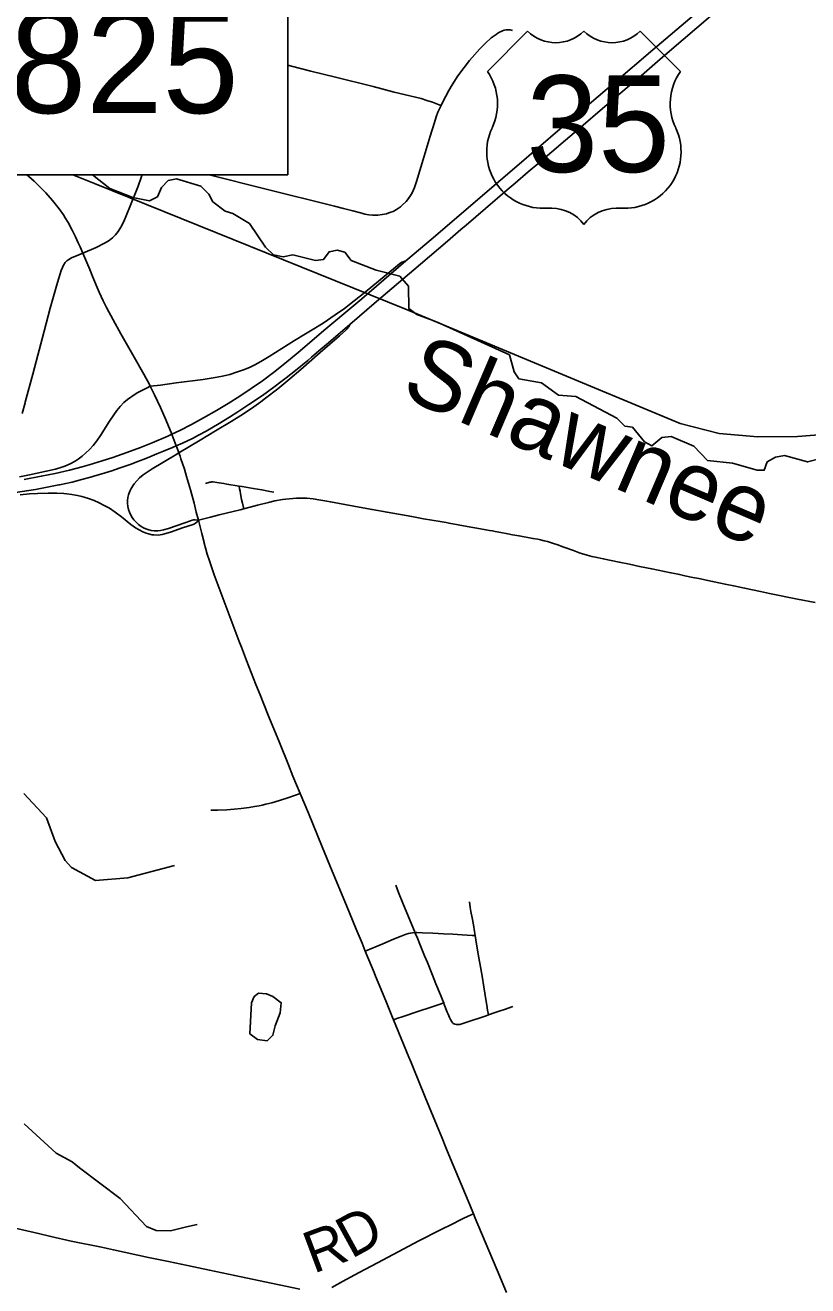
# Model space of a CAD drawing. Extents: x -1.4 to 35.4, y 0 to 22.
# Drawn here: x 13.773 to 14.841, y 16.794 to 18.515 of the extents above; entities that cross this region are included whole.
import ezdxf

# ---------------------------------------------------------------- set-up
doc = ezdxf.new("R2010")
doc.units = 0
for name, color, linetype in [('GM_X_City_Street', 7, 'Continuous'), ('GM_X_County_Road', 7, 'Continuous'), ('GM_X_Interchange_Ramps', 7, 'Continuous'), ('GM_X_Minor_Lake', 7, 'Continuous'), ('GM_X_Minor_River', 7, 'Continuous'), ('GM_X_Minor_River_Text', 7, 'Continuous'), ('GM_X_Rail_Line', 7, 'Continuous'), ('GM_X_Township_Road', 7, 'Continuous'), ('GM_X_Township_Road_Text', 7, 'Continuous'), ('GM_X_US_Location', 7, 'Continuous'), ('GM_X_US_Route', 7, 'Continuous'), ('GM_X_US_Shield', 7, 'Continuous'), ('SH_Data', 7, 'Continuous')]:
    doc.layers.add(name, color=color, linetype=linetype)

msp = doc.modelspace()

# ---------------------------------------------------------------- linework, layer by layer
at = {"layer": 'GM_X_City_Street'}
for points in [[(14.0238, 18.3109), (14.1, 18.2917), (14.1952, 18.2679), (14.2072, 18.2648), (14.22, 18.2615), (14.2306, 18.2587), (14.2338, 18.2578), (14.2365, 18.2572), (14.2392, 18.2566), (14.2421, 18.2562), (14.2469, 18.2557), (14.2505, 18.2555), (14.2542, 18.2558), (14.2603, 18.2564), (14.2633, 18.257), (14.2663, 18.2577), (14.2693, 18.2587), (14.2721, 18.2596), (14.2751, 18.2609), (14.2776, 18.2622), (14.2796, 18.2633), (14.2823, 18.2651), (14.285, 18.2671), (14.2875, 18.2693), (14.2928, 18.2744), (14.2963, 18.2786), (14.2997, 18.2837), (14.3014, 18.287), (14.3031, 18.2902), (14.3044, 18.2933), (14.3053, 18.2961), (14.3071, 18.3017), (14.3162, 18.3315), (14.3255, 18.3637), (14.3314, 18.3821), (14.3341, 18.3899), (14.3364, 18.3963), (14.3393, 18.4027), (14.3405, 18.4053), (14.3421, 18.4087), (14.3469, 18.4181), (14.3512, 18.4259), (14.3559, 18.4338), (14.3637, 18.4458), (14.372, 18.4575), (14.3794, 18.4667), (14.3933, 18.4827), (14.4013, 18.4906), (14.4092, 18.4977), (14.4157, 18.5026), (14.4182, 18.5043), (14.4205, 18.5056), (14.4225, 18.5066), (14.4246, 18.5075), (14.4269, 18.5082), (14.4299, 18.5088), (14.4324, 18.5089), (14.4348, 18.5087), (14.438, 18.508)], [(14.1312, 18.4607), (14.1363, 18.459), (14.1629, 18.4524), (14.1966, 18.444), (14.2479, 18.4312), (14.2767, 18.4238), (14.3136, 18.4148), (14.3213, 18.4125), (14.3291, 18.4099), (14.3381, 18.4063), (14.3405, 18.4053)], [(13.8515, 18.204), (13.8699, 18.2114), (13.8822, 18.218), (13.8876, 18.2213), (13.892, 18.2249), (13.896, 18.2289), (13.8996, 18.2333), (13.9033, 18.2392), (13.9073, 18.247), (13.9155, 18.2672), (13.9269, 18.2954), (13.9312, 18.3071), (13.9324, 18.3109)]]:
    msp.add_lwpolyline(points, dxfattribs=at)
at = {"layer": 'GM_X_County_Road'}
msp.add_line((13.7729, 18.0004), (13.783, 18.0386), dxfattribs=at)
for points in [[(13.783, 18.0386), (13.7987, 18.0973), (13.807, 18.1287), (13.8171, 18.1637), (13.8219, 18.1803), (13.8235, 18.1842), (13.8252, 18.1876), (13.8275, 18.191), (13.8297, 18.1932), (13.8323, 18.1952), (13.8359, 18.1973), (13.8461, 18.2017), (13.8515, 18.204)], [(13.7687, 17.9849), (13.7726, 17.9994), (13.7729, 18.0004)]]:
    msp.add_lwpolyline(points, dxfattribs=at)
at = {"layer": 'GM_X_Interchange_Ramps'}
for points in [[(14.2924, 18.1931), (14.2887, 18.1919), (14.2872, 18.1914), (14.2857, 18.1906), (14.2838, 18.1892), (14.2757, 18.1825), (14.2657, 18.1742), (14.237, 18.1506), (14.222, 18.1385), (14.2087, 18.1284), (14.196, 18.1194), (14.1794, 18.1084), (14.1647, 18.0991), (14.1557, 18.0936), (14.1403, 18.0843), (14.1061, 18.0628), (14.0944, 18.0558), (14.0862, 18.0513), (14.0789, 18.0478), (14.0709, 18.0445), (14.0615, 18.0412), (14.052, 18.0383), (14.0423, 18.0359), (14.032, 18.0339), (14.016, 18.0314), (13.979, 18.0266), (13.9575, 18.0237), (13.9435, 18.022)], [(13.9776, 17.928), (13.9826, 17.931), (14.0118, 17.9486), (14.0326, 17.9611), (14.0539, 17.974), (14.0708, 17.9846), (14.0848, 17.9939), (14.0944, 18.0007), (14.1009, 18.0056), (14.1178, 18.0187), (14.134, 18.032), (14.1491, 18.0449), (14.1756, 18.0681), (14.2019, 18.0911), (14.2105, 18.0987), (14.2123, 18.1004), (14.2134, 18.1018), (14.2145, 18.1034), (14.216, 18.1063)], [(13.9435, 18.022), (13.9391, 18.0198), (13.9294, 18.0151), (13.9264, 18.0134), (13.9228, 18.0112), (13.9125, 18.0039), (13.9076, 17.9997), (13.9025, 17.9942), (13.898, 17.989), (13.8936, 17.9831), (13.8878, 17.9743), (13.8756, 17.9548), (13.8707, 17.9476), (13.8657, 17.9413), (13.8607, 17.9357), (13.8558, 17.931), (13.8506, 17.9265), (13.8451, 17.9224), (13.841, 17.9198), (13.8344, 17.9162), (13.827, 17.913), (13.8229, 17.9116), (13.814, 17.909), (13.7994, 17.9057), (13.7785, 17.9009), (13.7648, 17.8985)], [(14.0092, 17.8391), (14.0047, 17.8394), (14.0027, 17.8394), (14.0008, 17.8391), (13.9983, 17.8384), (13.9907, 17.8356), (13.9684, 17.8278), (13.9618, 17.8259), (13.9576, 17.8251), (13.9539, 17.8247), (13.9489, 17.8247), (13.9446, 17.8252), (13.9416, 17.8259), (13.9375, 17.8272), (13.9341, 17.8288), (13.9309, 17.8307), (13.9274, 17.8333), (13.9242, 17.8362), (13.9213, 17.8395), (13.9187, 17.843), (13.9168, 17.8462), (13.915, 17.8501), (13.9138, 17.8537), (13.9129, 17.8579), (13.9125, 17.8622), (13.9126, 17.866), (13.9131, 17.8703), (13.9139, 17.8739), (13.9155, 17.8786), (13.9168, 17.8814), (13.9196, 17.8862), (13.9214, 17.8888), (13.925, 17.893), (13.929, 17.8969), (13.9338, 17.9009), (13.9394, 17.9049), (13.9462, 17.9092), (13.9776, 17.928)], [(13.7661, 17.8739), (13.7785, 17.8751), (13.7897, 17.8757), (13.804, 17.876), (13.8162, 17.8759), (13.8256, 17.8755), (13.8298, 17.8751), (13.8364, 17.8742), (13.8413, 17.8734), (13.8441, 17.8728), (13.8499, 17.8715), (13.8533, 17.8705), (13.8592, 17.8687), (13.8668, 17.8661), (13.8738, 17.863), (13.8807, 17.8594), (13.8877, 17.8554), (13.8956, 17.85), (13.9041, 17.8435), (13.9168, 17.8334), (13.9234, 17.8288), (13.9282, 17.8259), (13.9332, 17.8234), (13.9378, 17.8215)], [(13.9378, 17.8215), (13.9413, 17.8204), (13.9462, 17.8193), (13.9486, 17.819), (13.9542, 17.8189), (13.9597, 17.8197), (13.9628, 17.8204), (13.9711, 17.8229), (13.9875, 17.8286), (14.0021, 17.8333), (14.0041, 17.8341), (14.0055, 17.8349), (14.007, 17.8363), (14.0092, 17.8391)]]:
    msp.add_lwpolyline(points, dxfattribs=at)
at = {"layer": 'GM_X_Minor_Lake'}
for points in [[(14.0796, 17.1378), (14.0901, 17.1297), (14.103, 17.1279), (14.1111, 17.1358), (14.1143, 17.1486), (14.1211, 17.1663), (14.1225, 17.18), (14.1108, 17.1885), (14.1022, 17.1925), (14.0912, 17.1934), (14.0854, 17.1886), (14.0818, 17.1799)], [(14.0818, 17.1799), (14.0796, 17.1378)]]:
    msp.add_lwpolyline(points, dxfattribs=at)
at = {"layer": 'GM_X_Minor_River'}
for points in [[(13.8645, 18.3109), (13.8882, 18.2923), (13.9199, 18.28), (13.9426, 18.2754), (13.9533, 18.2809), (13.9589, 18.2934), (13.9682, 18.3031), (13.9792, 18.3052), (14.0128, 18.2955), (14.0236, 18.2843), (14.0288, 18.2739), (14.0457, 18.2611), (14.0562, 18.2579), (14.0792, 18.2442), (14.101, 18.2119), (14.1118, 18.2015), (14.1251, 18.1989), (14.138, 18.2014), (14.169, 18.194), (14.1801, 18.1953), (14.1878, 18.2058), (14.1989, 18.2079), (14.2091, 18.2051), (14.218, 18.1939), (14.252, 18.1808), (14.2841, 18.1726), (14.296, 18.1588), (14.2966, 18.128), (14.3075, 18.1202), (14.3286, 18.1122), (14.3384, 18.1083), (14.4338, 18.0649), (14.4406, 18.0419), (14.4469, 18.032), (14.4775, 18.0269), (14.5008, 18.0098), (14.5247, 18.0082), (14.5804, 17.9784), (14.5916, 17.9676), (14.6018, 17.9662), (14.6185, 17.9462), (14.6283, 17.9407), (14.6422, 17.9519), (14.6547, 17.9536), (14.6856, 17.9401), (14.7043, 17.9208), (14.7384, 17.9172), (14.772, 17.9075), (14.7819, 17.9073), (14.7859, 17.9186), (14.7974, 17.9253), (14.8096, 17.9274), (14.8409, 17.9188), (14.8623, 17.9245)], [(13.7708, 17.4659), (13.8018, 17.4327), (13.8138, 17.4003), (13.8274, 17.3746), (13.8359, 17.3646), (13.8687, 17.3469), (13.9131, 17.3507), (13.9768, 17.3674)], [(13.7715, 17.0148), (13.8152, 16.9745), (13.837, 16.9627), (13.8468, 16.9546), (13.9026, 16.913), (13.9384, 16.8744), (13.9516, 16.8689), (13.971, 16.8685), (13.9931, 16.8739), (14.0076, 16.8774)]]:
    msp.add_lwpolyline(points, dxfattribs=at)
at = {"layer": 'GM_X_Rail_Line'}
msp.add_lwpolyline([(13.8379, 18.3109), (13.8672, 18.299), (14.2911, 18.1278), (14.6669, 17.9711), (14.7201, 17.9576), (14.7731, 17.9529), (14.8273, 17.9533), (15.001, 17.9673)], dxfattribs=at)
at = {"layer": 'GM_X_Township_Road'}
for points in [[(14.019, 17.8894), (14.0236, 17.8908), (14.025, 17.891), (14.0262, 17.8912), (14.0278, 17.8913), (14.0294, 17.8913), (14.0344, 17.8907), (14.0441, 17.8891)], [(14.0441, 17.8891), (14.048, 17.8885), (14.0651, 17.8857)], [(14.0712, 17.8547), (14.0694, 17.8623), (14.0682, 17.8674), (14.0666, 17.8753), (14.0661, 17.8786), (14.0656, 17.8821), (14.0651, 17.8857)], [(14.0651, 17.8857), (14.0688, 17.885), (14.0841, 17.8826), (14.0958, 17.8806), (14.1068, 17.8785), (14.1123, 17.8775)], [(14.0712, 17.8547), (14.0661, 17.8534), (14.0378, 17.8463), (14.0257, 17.8432), (14.0092, 17.8391)], [(14.1847, 17.8649), (14.1737, 17.8669), (14.1658, 17.8681), (14.1573, 17.869), (14.1495, 17.8694), (14.143, 17.8693), (14.1332, 17.8684), (14.124, 17.8673), (14.1136, 17.8654), (14.1052, 17.8635), (14.0901, 17.8597), (14.0712, 17.8547)], [(14.8513, 17.7266), (14.8274, 17.7313), (14.789, 17.7391), (14.7769, 17.7417), (14.755, 17.7463), (14.7403, 17.7493), (14.7307, 17.7515), (14.7112, 17.7556), (14.6927, 17.7593), (14.6842, 17.761), (14.6733, 17.7633), (14.6642, 17.7652), (14.6545, 17.7673), (14.6283, 17.7726), (14.6113, 17.7761), (14.5979, 17.7789), (14.5839, 17.7819), (14.5621, 17.7864), (14.5536, 17.7881), (14.5463, 17.7897), (14.5402, 17.7912), (14.5356, 17.7926), (14.5307, 17.7942), (14.5213, 17.7976), (14.5081, 17.8025), (14.4988, 17.8058), (14.4953, 17.807), (14.4859, 17.8099), (14.4812, 17.8111), (14.4763, 17.8122), (14.4727, 17.813), (14.4661, 17.8143), (14.4472, 17.8176), (14.4381, 17.8192), (14.4316, 17.8204), (14.4223, 17.8221), (14.4145, 17.8236), (14.4108, 17.8244), (14.4067, 17.8251), (14.4019, 17.8261), (14.3946, 17.8274), (14.3761, 17.8307), (14.3516, 17.835), (14.3474, 17.8358), (14.3395, 17.8372), (14.3165, 17.8412), (14.3009, 17.844), (14.2668, 17.8499), (14.2463, 17.8536), (14.2289, 17.8569), (14.2018, 17.8618), (14.1896, 17.864), (14.1847, 17.8649)], [(14.0262, 17.4432), (14.036, 17.4431), (14.0482, 17.4435), (14.0582, 17.4444), (14.0678, 17.4454), (14.0785, 17.4468), (14.0858, 17.4479), (14.0924, 17.4491), (14.0965, 17.4499), (14.1014, 17.4511), (14.1095, 17.4533), (14.1201, 17.4565), (14.1326, 17.4605), (14.1481, 17.466)], [(14.3049, 17.2759), (14.3041, 17.2779), (14.296, 17.2974), (14.2883, 17.316), (14.2826, 17.3305), (14.2788, 17.3405)], [(14.3871, 17.2719), (14.3862, 17.2772), (14.3847, 17.2863), (14.3829, 17.2959), (14.3814, 17.3045), (14.3805, 17.31), (14.3793, 17.3181)], [(14.2371, 17.2507), (14.2613, 17.2607), (14.2758, 17.267), (14.2859, 17.2711), (14.293, 17.2738), (14.296, 17.2747), (14.2987, 17.2753), (14.3018, 17.2758), (14.3049, 17.2759)], [(14.3049, 17.2759), (14.3073, 17.276), (14.3152, 17.2756), (14.3292, 17.275), (14.3438, 17.2744), (14.3565, 17.2736), (14.3695, 17.2728), (14.3831, 17.2721), (14.3871, 17.2719)], [(14.3442, 17.1798), (14.3426, 17.184), (14.3398, 17.191), (14.3334, 17.2061), (14.3288, 17.2177), (14.3219, 17.2349), (14.3181, 17.2441), (14.3114, 17.26), (14.3082, 17.2682), (14.3049, 17.2759)], [(14.4052, 17.1635), (14.4041, 17.1699), (14.4029, 17.1767), (14.4016, 17.1846), (14.399, 17.2018), (14.3965, 17.2165), (14.3935, 17.2343), (14.3919, 17.2435), (14.388, 17.2661), (14.3871, 17.2719)], [(14.2756, 17.1569), (14.2815, 17.1589), (14.2876, 17.1609), (14.3104, 17.1685), (14.3257, 17.1736), (14.338, 17.1778), (14.3442, 17.1798)], [(14.3614, 17.1503), (14.3594, 17.1508), (14.3584, 17.1511), (14.3573, 17.1517), (14.3563, 17.1527), (14.3556, 17.1535), (14.3547, 17.1548), (14.3535, 17.1571), (14.3521, 17.1601), (14.3503, 17.1645), (14.3491, 17.1674), (14.345, 17.1777), (14.3442, 17.1798)], [(14.4052, 17.1635), (14.4143, 17.1667), (14.4214, 17.1691), (14.4273, 17.171), (14.4388, 17.1749)], [(14.3614, 17.1503), (14.3634, 17.1503), (14.3651, 17.1505), (14.366, 17.1506), (14.3731, 17.1528), (14.3855, 17.1569), (14.3926, 17.1592), (14.402, 17.1624), (14.4052, 17.1635)], [(13.4893, 16.9332), (13.4935, 16.9321), (13.4973, 16.9311), (13.501, 16.93), (13.5162, 16.9265), (13.5514, 16.9187), (13.5808, 16.9121), (13.6177, 16.9038), (13.7018, 16.8849), (13.7471, 16.8752), (13.7911, 16.8649), (13.808, 16.8611), (13.8357, 16.8547), (13.877, 16.8461), (13.8932, 16.8426), (13.9411, 16.8323), (13.9684, 16.8268), (13.9945, 16.8212), (14.0243, 16.8149), (14.0589, 16.8076), (14.0912, 16.801), (14.1476, 16.7888)], [(14.1915, 16.7914), (14.2062, 16.7995), (14.2286, 16.8117), (14.2538, 16.825), (14.2753, 16.8362), (14.3104, 16.8548), (14.3391, 16.8696), (14.3575, 16.8788), (14.3652, 16.8826), (14.3708, 16.8853), (14.3775, 16.8885), (14.3848, 16.8919)]]:
    msp.add_lwpolyline(points, dxfattribs=at)
at = {"layer": 'GM_X_US_Route'}
for points in [[(14.6295, 18.4813), (14.686, 18.5293), (14.7412, 18.5765), (14.7793, 18.6094), (14.7987, 18.6261), (14.8043, 18.6311), (14.8201, 18.6454), (14.8313, 18.6561), (14.8404, 18.6656), (14.8559, 18.6824)], [(14.6493, 18.477), (14.7117, 18.5302), (14.726, 18.5422), (14.7364, 18.5511), (14.7657, 18.576), (14.7836, 18.5914), (14.8096, 18.6137), (14.8184, 18.6214), (14.8351, 18.6372), (14.8409, 18.6428), (14.8488, 18.6507)], [(14.2924, 18.1931), (14.3297, 18.2247), (14.4003, 18.2854), (14.4439, 18.3225), (14.5033, 18.3734), (14.5765, 18.436), (14.6295, 18.4813)], [(14.3126, 18.1889), (14.3492, 18.2202), (14.3676, 18.236), (14.3747, 18.2421), (14.4012, 18.2646), (14.4309, 18.2901), (14.4417, 18.2994), (14.4596, 18.3148), (14.4729, 18.326), (14.4828, 18.3345), (14.4918, 18.3421), (14.5106, 18.3583), (14.5315, 18.376), (14.5612, 18.4014), (14.5835, 18.4204), (14.6142, 18.4466), (14.6362, 18.4657), (14.6493, 18.477)], [(13.8474, 18.2134), (13.8453, 18.218), (13.8414, 18.2262), (13.8371, 18.2352), (13.8314, 18.2455), (13.8275, 18.2522), (13.8249, 18.2562), (13.8192, 18.2642), (13.81, 18.2759), (13.8011, 18.2862), (13.7916, 18.2957), (13.7849, 18.302), (13.7779, 18.3084), (13.7751, 18.3109)], [(13.8515, 18.204), (13.8479, 18.2125), (13.8474, 18.2134)], [(13.8712, 18.1567), (13.8651, 18.1712), (13.8609, 18.1815), (13.8515, 18.204)], [(13.9674, 17.9541), (13.973, 17.9567), (13.9837, 17.9617), (13.9998, 17.9699), (14.0163, 17.9787), (14.0341, 17.9888), (14.0501, 17.9984), (14.0659, 18.0084), (14.0814, 18.0188), (14.0967, 18.0296), (14.1116, 18.0407), (14.1273, 18.053), (14.1456, 18.068), (14.1834, 18.1003), (14.2324, 18.1416), (14.2924, 18.1931)], [(13.9739, 17.9385), (13.9791, 17.9408), (13.9876, 17.9445), (13.9943, 17.9476), (14.001, 17.9509), (14.0093, 17.9551), (14.0197, 17.9607), (14.0374, 17.971), (14.0517, 17.9797), (14.0631, 17.9871), (14.0782, 17.997), (14.0966, 18.0096), (14.1122, 18.0209), (14.1237, 18.0294), (14.1292, 18.0335), (14.1419, 18.0434), (14.1586, 18.0573), (14.1638, 18.0617), (14.1737, 18.0702), (14.1841, 18.079), (14.216, 18.1063), (14.2525, 18.1377), (14.2885, 18.1683), (14.3126, 18.1889)], [(13.9435, 18.022), (13.9423, 18.0245), (13.9347, 18.0387), (13.9197, 18.0648), (13.9032, 18.0937), (13.8927, 18.1126), (13.8839, 18.1298), (13.8793, 18.1389), (13.8738, 18.1507), (13.8712, 18.1567)], [(13.9842, 17.9266), (13.9826, 17.931), (13.9798, 17.9389), (13.9791, 17.9408), (13.9736, 17.9552), (13.973, 17.9567), (13.9653, 17.9754), (13.9575, 17.9932), (13.9494, 18.0102), (13.9435, 18.022)], [(13.7712, 17.8949), (13.7946, 17.8992), (13.8135, 17.9029), (13.8335, 17.9076), (13.8504, 17.912), (13.86, 17.9147), (13.8778, 17.9201), (13.8926, 17.9249), (13.9114, 17.9314), (13.9301, 17.9384), (13.9462, 17.9449), (13.9674, 17.9541)], [(13.8947, 17.9079), (13.904, 17.9111), (13.9081, 17.9125), (13.9174, 17.9158), (13.925, 17.9186), (13.9354, 17.9226), (13.9429, 17.9257), (13.9527, 17.9297), (13.9616, 17.9332), (13.9739, 17.9385)], [(14.0092, 17.8391), (14.0064, 17.8502), (14.0033, 17.8624), (13.9986, 17.8804), (13.9932, 17.8989), (13.9901, 17.909), (13.9854, 17.9231), (13.9842, 17.9266)], [(13.8195, 17.8874), (13.8367, 17.8912), (13.8481, 17.8941), (13.8637, 17.8984), (13.8679, 17.8996), (13.8762, 17.902), (13.8821, 17.9039), (13.891, 17.9067), (13.8947, 17.9079)], [(13.6744, 17.8663), (13.6945, 17.8687), (13.7231, 17.8721), (13.7388, 17.8742), (13.7463, 17.8752), (13.7597, 17.8771), (13.7867, 17.8812), (13.8026, 17.884), (13.8185, 17.8872), (13.8195, 17.8874)], [(14.0173, 17.8077), (14.0171, 17.8086), (14.0138, 17.8208), (14.011, 17.8319), (14.0092, 17.8391)], [(14.0878, 17.6147), (14.0751, 17.6474), (14.0679, 17.6657), (14.0649, 17.6735), (14.0307, 17.7645), (14.0243, 17.7834), (14.0214, 17.7926), (14.0194, 17.7997), (14.0173, 17.8077)], [(14.0975, 17.5903), (14.0934, 17.6006), (14.0878, 17.6147)], [(14.4297, 16.7845), (14.4171, 16.8149), (14.4006, 16.8538), (14.3873, 16.8859), (14.3848, 16.8919), (14.3798, 16.9043), (14.3679, 16.9324), (14.3573, 16.9582), (14.3514, 16.9726), (14.3473, 16.9823), (14.3421, 16.995), (14.3351, 17.0116), (14.3189, 17.0512), (14.3024, 17.0915), (14.2996, 17.0984), (14.2966, 17.1059), (14.2892, 17.1237), (14.2756, 17.1569), (14.2753, 17.1576), (14.265, 17.1829), (14.2548, 17.2076), (14.2512, 17.2162), (14.2491, 17.2214), (14.2456, 17.23), (14.2371, 17.2507), (14.2328, 17.2613), (14.2249, 17.2806), (14.2114, 17.313), (14.1921, 17.3599), (14.1784, 17.3932), (14.1595, 17.4392), (14.1481, 17.466), (14.1384, 17.4896), (14.1321, 17.5049), (14.1199, 17.5355), (14.1054, 17.5706), (14.0975, 17.5903)]]:
    msp.add_lwpolyline(points, dxfattribs=at)
at = {"layer": 'GM_X_US_Shield'}
for p, q in [((14.4587, 18.5068), (14.4038, 18.4519)), ((14.6674, 18.4519), (14.6125, 18.5068)), ((14.4807, 18.2651), (14.4917, 18.2651)), ((14.5795, 18.2651), (14.5905, 18.2651))]:
    msp.add_line(p, q, dxfattribs=at)
for centre, radius, start, end in [((14.4971, 18.5461), 0.0549, 225.573, 314.427), ((14.5741, 18.5461), 0.0549, 225.573, 314.427), ((14.3408, 18.4078), 0.0769, 334.5471, 35.0009), ((14.7304, 18.4078), 0.0769, 144.9991, 205.4529), ((14.4798, 18.342), 0.0769, 154.8319, 270.6383), ((14.5914, 18.342), 0.0769, 269.3617, 25.1681), ((14.4917, 18.2102), 0.0549, 36.8699, 90), ((14.5795, 18.2102), 0.0549, 90, 143.1301)]:
    msp.add_arc(centre, radius, start, end, dxfattribs=at)
at = {"layer": 'SH_Data'}
msp.add_lwpolyline([(14.1312, 18.6309), (12.8612, 18.6309), (12.8612, 18.5134), (12.2585, 18.0339), (12.8612, 18.3909), (12.8612, 18.3109), (14.1312, 18.3109)], close=True, dxfattribs=at)

# ---------------------------------------------------------------- texts
at = {"layer": 'GM_X_Minor_River_Text'}
msp.add_text('Shawnee', height=0.09469, rotation=336.8246, dxfattribs=at).set_placement((14.2827, 18.0091))
at = {"layer": 'GM_X_Township_Road_Text'}
for s, rotation, p in [('D', 28.7349, (14.2181, 16.8298)), ('R', 20.504, (14.1664, 16.8098))]:
    msp.add_text(s, height=0.0568, rotation=rotation, dxfattribs=at).set_placement(p)
at = {"layer": 'GM_X_US_Location'}
for s in ['0', '/']:
    msp.add_text(s, height=0.000189, dxfattribs=at).set_placement((14.5355, 18.3795))
msp.add_text('35', height=0.000189, rotation=0, dxfattribs=at).set_placement((14.4964, 18.3403))
at = {"layer": 'GM_X_US_Shield'}
msp.add_text('35', height=0.13184, dxfattribs=at).set_placement((14.457, 18.3146))
at = {"layer": 'SH_Data'}
msp.add_text('GRE-42-0825', height=0.14, dxfattribs=at).set_placement((12.9093, 18.3951))

doc.saveas('drawing.dxf')
